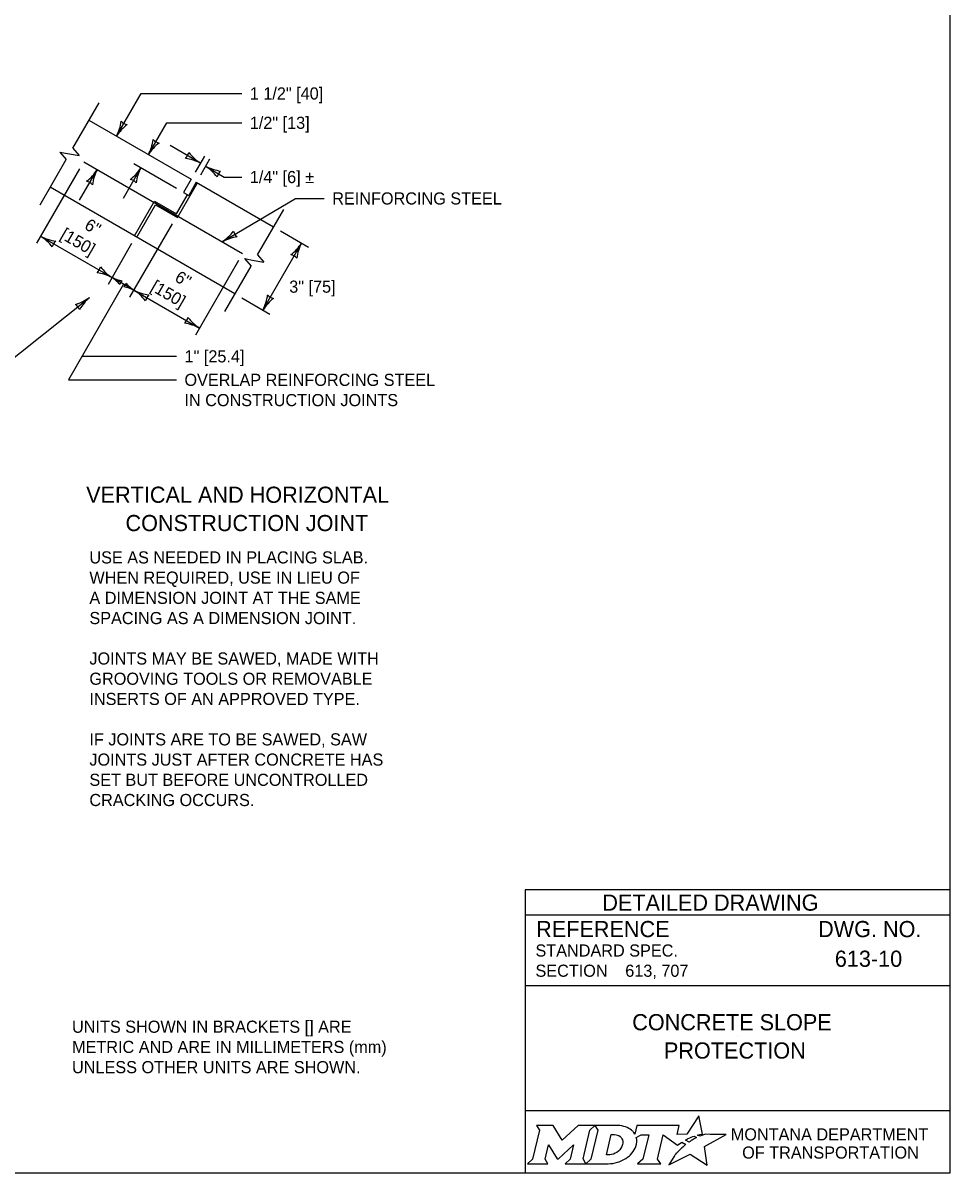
# Model space of a CAD drawing. Extents: x 49991.4 to 50021, y 49987.6 to 50011.4.
# Drawn here: x 50012.17 to 50016.75, y 49987.8 to 49993.49 of the extents above; entities that cross this region are included whole.
import ezdxf

# ---------------------------------------------------------------- set-up
doc = ezdxf.new("R2010")
doc.units = 0
for name, color, linetype in [('Default', 7, 'Continuous'), ('Level 1', 7, 'Continuous'), ('Level 2', 7, 'Continuous'), ('Level 3', 7, 'Continuous'), ('Level 5', 7, 'Continuous'), ('Level 6', 7, 'Continuous')]:
    doc.layers.add(name, color=color, linetype=linetype)

msp = doc.modelspace()

# ---------------------------------------------------------------- linework, layer by layer
at = {"layer": 'Default'}
for points in [[(50015.5126, 49987.9811), (50015.5023, 49987.9867), (50015.5139, 49987.9895), (50015.5255, 49987.9915), (50015.5081, 49988.0816), (50015.4486, 49987.9903), (50015.4013, 49987.9896), (50015.4116, 49988.0337), (50015.2024, 49988.0338), (50015.1923, 49987.9913), (50015.1865, 49987.9996)], [(50014.7056, 49988.0338), (50014.7197, 49988.0104), (50014.6862, 49987.8671), (50014.6605, 49987.8446), (50014.7621, 49987.8446), (50014.7486, 49987.8674), (50014.7648, 49987.9375), (50014.8085, 49987.8685), (50014.8138, 49987.8685), (50014.8889, 49987.938), (50014.8725, 49987.8669), (50014.8478, 49987.8449), (50014.9494, 49987.8449), (50014.9356, 49987.8682), (50014.9688, 49988.0106)], [(50014.9688, 49988.0106), (50014.9941, 49988.0338), (50014.9117, 49988.0338), (50014.8321, 49987.9608), (50014.7876, 49988.0335), (50014.7056, 49988.0338)], [(50015.1077, 49988.0338), (50014.9941, 49988.0338), (50015.0088, 49988.0109), (50014.9749, 49987.8671), (50014.9494, 49987.8449), (50015.06, 49987.8449)], [(50015.1317, 49987.9471), (50015.1305, 49987.939), (50015.1273, 49987.9297), (50015.1231, 49987.9215), (50015.1175, 49987.914), (50015.111, 49987.9071), (50015.1031, 49987.9008), (50015.0948, 49987.8961), (50015.0857, 49987.8922), (50015.0766, 49987.8899), (50015.0674, 49987.889), (50015.0515, 49987.889), (50015.0751, 49987.989), (50015.0911, 49987.989), (50015.0987, 49987.9884), (50015.1063, 49987.9865), (50015.1129, 49987.9835), (50015.119, 49987.9793), (50015.1238, 49987.9743), (50015.1275, 49987.9683), (50015.1302, 49987.9621), (50015.1318, 49987.9547), (50015.1318, 49987.9517), (50015.1317, 49987.9471)], [(50015.1991, 49987.9747), (50015.2237, 49987.9878), (50015.2606, 49987.9878), (50015.232, 49987.8673), (50015.2045, 49987.8446), (50015.3207, 49987.8446), (50015.3037, 49987.8675), (50015.3319, 49987.9877), (50015.4032, 49987.936), (50015.4243, 49987.9511), (50015.444, 49987.9402)], [(50015.3882, 49987.8843), (50015.3729, 49987.8599), (50015.3682, 49987.8524), (50015.3624, 49987.8438), (50015.3601, 49987.8395), (50015.4654, 49987.8926), (50015.5493, 49987.8375), (50015.5362, 49987.9302), (50015.6431, 49987.9886), (50015.5938, 49987.9894), (50015.5637, 49987.9898), (50015.5429, 49987.9901), (50015.5361, 49987.9886), (50015.5312, 49987.9874), (50015.5228, 49987.9851), (50015.5126, 49987.9811)], [(50015.4622, 49987.9535), (50015.4598, 49987.9518), (50015.4415, 49987.9614), (50015.4518, 49987.9671), (50015.4559, 49987.9693), (50015.4645, 49987.9733), (50015.4702, 49987.9759), (50015.4781, 49987.9789), (50015.4854, 49987.9816), (50015.4972, 49987.9742), (50015.4932, 49987.9721), (50015.4886, 49987.9696), (50015.4844, 49987.9674), (50015.4794, 49987.9645), (50015.4775, 49987.9634), (50015.4748, 49987.9618), (50015.4723, 49987.9604), (50015.47, 49987.9588), (50015.4674, 49987.957), (50015.4647, 49987.9552), (50015.4622, 49987.9535)], [(50015.1057, 49987.8522), (50015.1141, 49987.8548), (50015.1271, 49987.8602), (50015.1475, 49987.8712)], [(50015.4021, 49987.9004), (50015.4021, 49987.9004)]]:
    msp.add_lwpolyline(points, dxfattribs=at)
for centre, radius, start, end in [((50015.0868, 49987.9727), 0.1183, 300.9103, 339.1383), ((50015.1308, 49987.9554), 0.0709, 339.5329, 15.8582)]:
    msp.add_arc(centre, radius, start, end, dxfattribs=at)
for centre, major_axis, ratio, start_param, end_param in [((50015.1056, 49987.9864), (0.0834, -0.0037), 0.568097, 0.61298, 1.570796), ((50015.1612, 49987.9937), (0.0361, -0.0295), 0.469099, 1.225588, 1.570796), ((50015.4329, 49987.9305), (-0.0112, -0.0097), 0.021651, 3.157348, 6.283185), ((50015.3952, 49987.8923), (-0.00694, -0.00806), 0.008222, 0, 3.137361), ((50015.4119, 49987.9106), (-0.0098, -0.0102), 0.016458, 3.141593, 6.279097), ((50015.0603, 49987.9932), (0, 0.1484), 0.987302, 3.139398, 3.456847)]:
    msp.add_ellipse(centre, major_axis=major_axis, ratio=ratio, start_param=start_param, end_param=end_param, dxfattribs=at)
at = {"layer": 'Level 1'}
for p, q in [((50012.4923, 49993.006), (50012.9975, 49992.7141)), ((50012.4665, 49992.7998), (50013.2518, 49992.3466)), ((50012.9975, 49992.7141), (50012.9601, 49992.6492)), ((50013.2145, 49992.1471), (50012.3006, 49992.6744)), ((50012.9305, 49992.5249), (50013.029, 49992.696)), ((50012.9601, 49992.6492), (50012.986, 49992.6341)), ((50013.0234, 49992.6992), (50012.986, 49992.6341)), ((50013.0234, 49992.6992), (50013.4056, 49992.4784)), ((50012.7175, 49992.4339), (50012.8161, 49992.6058)), ((50012.8161, 49992.6058), (50012.9256, 49992.5426)), ((50012.9256, 49992.5426), (50012.9803, 49992.6374)), ((50012.7292, 49992.4271), (50012.8216, 49992.5876)), ((50012.8216, 49992.5876), (50012.9305, 49992.5249))]:
    msp.add_line(p, q, dxfattribs=at)
msp.add_lwpolyline([(49999.3835, 49998.9992), (50016.7501, 49998.9992), (50016.7501, 49987.7988), (49999.3835, 49987.7988)], close=True, dxfattribs=at)
at = {"layer": 'Level 3'}
for p, q in [((50012.6287, 49992.9272), (50012.751, 49993.1387)), ((50012.751, 49993.1387), (50013.2478, 49993.1387)), ((50012.7865, 49992.836), (50012.8771, 49992.9936)), ((50012.8771, 49992.9936), (50013.2478, 49992.9936)), ((50013.0437, 49992.7942), (50012.8934, 49992.8807)), ((50013.0637, 49992.8288), (50013.0175, 49992.7487)), ((50012.4465, 49992.7652), (50012.2337, 49992.3975)), ((50012.4465, 49992.6115), (50012.5332, 49992.7617)), ((50012.6626, 49992.6208), (50012.7492, 49992.7711)), ((50012.9255, 49992.6692), (50012.7146, 49992.7912)), ((50013.0892, 49992.8132), (50013.0434, 49992.7338)), ((50013.0692, 49992.7786), (50013.1618, 49992.7252)), ((50013.1618, 49992.7252), (50013.2478, 49992.7252)), ((50013.1509, 49992.4048), (50013.5142, 49992.6194)), ((50013.5142, 49992.6194), (50013.6555, 49992.6194)), ((50012.6946, 49992.1312), (50012.9048, 49992.4935)), ((50012.2537, 49992.4321), (50012.6066, 49992.2281)), ((50013.4402, 49992.4585), (50013.5782, 49992.3787)), ((50012.7033, 49992.3959), (50012.5868, 49992.1934)), ((50013.3526, 49992.0675), (50013.5436, 49992.3987)), ((50013.2318, 49992.312), (50013.0189, 49991.9438)), ((50012.6628, 49992.1958), (50012.3918, 49991.722)), ((50012.7147, 49992.1658), (50012.6066, 49992.2281)), ((50012.7147, 49992.1658), (50013.0389, 49991.9784)), ((50011.5449, 49991.371), (50012.4953, 49992.1298)), ((50013.2492, 49992.1271), (50013.3873, 49992.0475)), ((50012.4583, 49991.8384), (50012.9252, 49991.8384)), ((50012.3918, 49991.722), (50012.9247, 49991.722))]:
    msp.add_line(p, q, dxfattribs=at)
for centre, radius, start, end in [((50012.4215, 49993.0336), 0.233, 332.8074, 352.0572), ((50012.6929, 49993.0382), 0.0548, 222.1189, 257.8412), ((50012.8165, 49992.8081), 0.2223, 127.4361, 147.6196), ((50012.579, 49992.9421), 0.233, 332.9081, 352.158), ((50012.9744, 49992.7173), 0.2223, 127.5368, 147.7203), ((50012.8504, 49992.9472), 0.0548, 222.2196, 257.942), ((50012.9326, 49992.8581), 0.0548, 312.2277, 347.95), ((50012.9376, 49992.5867), 0.233, 62.9162, 82.166), ((50013.1624, 49992.9822), 0.2223, 217.5449, 237.7284), ((50012.3454, 49992.8807), 0.2223, 307.463, 327.6465), ((50012.3454, 49992.8807), 0.2223, 307.463, 327.6465), ((50012.7405, 49992.6553), 0.233, 152.8343, 172.0842), ((50012.7405, 49992.6553), 0.233, 152.8343, 172.0842), ((50012.5612, 49992.8898), 0.2223, 307.5459, 327.7294), ((50012.9566, 49992.6651), 0.233, 152.9172, 172.167), ((50012.9503, 49992.5907), 0.2223, 37.4907, 57.6742), ((50013.1755, 49992.9859), 0.233, 242.862, 262.1118), ((50012.4691, 49992.6507), 0.0548, 42.1458, 77.8682), ((50012.4691, 49992.6507), 0.0548, 42.1458, 77.8682), ((50012.6852, 49992.66), 0.0548, 42.2287, 77.9511), ((50013.1803, 49992.7145), 0.0548, 132.1735, 167.8958), ((50012.1346, 49992.2444), 0.2223, 37.4296, 57.6131), ((50012.3602, 49992.6393), 0.233, 242.8009, 262.0507), ((50013.0227, 49992.5993), 0.233, 303.3975, 322.6474), ((50013.256, 49992.2089), 0.2223, 98.0262, 118.2097), ((50013.2613, 49992.47), 0.0548, 192.709, 228.4314), ((50012.3647, 49992.368), 0.0548, 132.1124, 167.8347), ((50013.3557, 49992.5176), 0.2223, 307.4958, 327.6793), ((50013.7509, 49992.2925), 0.233, 152.8671, 172.117), ((50013.4795, 49992.2877), 0.0548, 42.1786, 77.901), ((50012.4958, 49992.2922), 0.0548, 312.1124, 347.8347), ((50012.5003, 49992.0208), 0.233, 62.8009, 82.0507), ((50012.7259, 49992.4158), 0.2223, 217.4296, 237.6131), ((50012.5275, 49992.1028), 0.1482, 37.4804, 57.6639), ((50012.6777, 49992.3663), 0.1553, 242.8517, 262.1016), ((50012.6808, 49992.1853), 0.0365, 132.1632, 167.8856), ((50012.6406, 49992.2085), 0.0365, 312.1632, 347.8856), ((50012.794, 49992.291), 0.1482, 217.4804, 237.6639), ((50012.6438, 49992.0276), 0.1553, 62.8517, 82.1016), ((50012.5956, 49991.9781), 0.2223, 37.4244, 57.6079), ((50012.8212, 49992.373), 0.233, 242.7957, 262.0456), ((50012.8257, 49992.1016), 0.0548, 132.1072, 167.8296), ((50013.1453, 49992.1737), 0.233, 332.8671, 352.117), ((50013.4167, 49992.1786), 0.0548, 222.1786, 257.901), ((50012.3638, 49992.3091), 0.2223, 286.0616, 306.2451), ((50012.3951, 49992.0498), 0.0548, 20.7444, 56.4667), ((50012.6495, 49991.9551), 0.233, 131.4329, 150.6827), ((50013.5405, 49991.9486), 0.2223, 127.4958, 147.6793), ((50012.9279, 49992.0426), 0.0548, 312.1072, 347.8296), ((50013.158, 49992.1662), 0.2223, 217.4244, 237.6079), ((50012.9324, 49991.7712), 0.233, 62.7957, 82.0456)]:
    msp.add_arc(centre, radius, start, end, dxfattribs=at)
at = {"layer": 'Level 5'}
for p, q in [((50016.7501, 49989.1988), (50014.6501, 49989.1988)), ((50014.6501, 49989.1988), (50014.6501, 49987.7988)), ((50016.7501, 49989.0738), (50014.6501, 49989.0738)), ((50016.3862, 49988.8587), (50016.3862, 49988.8587)), ((50015.1444, 49988.7993), (50015.1444, 49988.7993)), ((50016.7501, 49988.7238), (50014.6501, 49988.7238)), ((50015.7001, 49988.4747), (50015.7001, 49988.4747)), ((50016.7501, 49988.1057), (50014.6501, 49988.1057))]:
    msp.add_line(p, q, dxfattribs=at)
at = {"layer": 'Level 6'}
for p, q in [((50012.4126, 49992.8682), (50012.5423, 49993.0926)), ((50012.3487, 49992.849), (50012.3964, 49992.8402)), ((50012.3487, 49992.849), (50012.3802, 49992.8121)), ((50012.3964, 49992.8402), (50012.4441, 49992.8314)), ((50012.4126, 49992.8683), (50012.4441, 49992.8314)), ((50012.2506, 49992.5878), (50012.3802, 49992.8121)), ((50013.3262, 49992.3409), (50013.4555, 49992.565)), ((50013.2623, 49992.3216), (50013.31, 49992.3128)), ((50013.2623, 49992.3216), (50013.2938, 49992.2847)), ((50013.31, 49992.3128), (50013.3577, 49992.304)), ((50013.3262, 49992.3409), (50013.3577, 49992.304)), ((50013.1646, 49992.0605), (50013.2938, 49992.2847))]:
    msp.add_line(p, q, dxfattribs=at)

# ---------------------------------------------------------------- texts
at = {"layer": 'Default'}
for s, p in [('MONTANA DEPARTMENT', (50015.6663, 49987.96)), ('OF TRANSPORTATION', (50015.7225, 49987.87))]:
    msp.add_text(s, height=0.06, dxfattribs=at).set_placement(p)
at = {"layer": 'Level 2'}
for s, height, p in [('1 1/2" [40]', 0.06, (50013.2878, 49993.1087)), ('1/2" [13]', 0.06, (50013.2878, 49992.9636)), ('1/4" [6] ±', 0.06, (50013.2878, 49992.6952)), ('REINFORCING STEEL', 0.06, (50013.6955, 49992.5894)), ('3" [75]', 0.06, (50013.4828, 49992.1531)), ('1" [25.4]', 0.06, (50012.9652, 49991.8084)), ('OVERLAP REINFORCING STEEL', 0.06, (50012.9647, 49991.692)), ('IN CONSTRUCTION JOINTS', 0.06, (50012.9647, 49991.592)), ('VERTICAL AND HORIZONTAL', 0.08, (50012.4788, 49991.1138)), ('CONSTRUCTION JOINT', 0.08, (50012.6732, 49990.9738)), ('USE AS NEEDED IN PLACING SLAB.', 0.06, (50012.4947, 49990.8138)), ('WHEN REQUIRED, USE IN LIEU OF', 0.06, (50012.4947, 49990.7138)), ('A DIMENSION JOINT AT THE SAME', 0.06, (50012.4947, 49990.6138)), ('SPACING AS A DIMENSION JOINT.', 0.06, (50012.4947, 49990.5138)), ('JOINTS MAY BE SAWED, MADE WITH', 0.06, (50012.4947, 49990.3138)), ('GROOVING TOOLS OR REMOVABLE', 0.06, (50012.4947, 49990.2138)), ('INSERTS OF AN APPROVED TYPE.', 0.06, (50012.4947, 49990.1138)), ('IF JOINTS ARE TO BE SAWED, SAW', 0.06, (50012.4947, 49989.9138)), ('JOINTS JUST AFTER CONCRETE HAS', 0.06, (50012.4947, 49989.8138)), ('SET BUT BEFORE UNCONTROLLED', 0.06, (50012.4947, 49989.7138)), ('CRACKING OCCURS.', 0.06, (50012.4947, 49989.6138)), ('613-10', 0.08, (50016.1806, 49988.8187)), ('613, 707', 0.06, (50015.1444, 49988.7693)), ('UNITS SHOWN IN BRACKETS [] ARE ', 0.06, (50012.4089, 49988.4924)), ('CONCRETE SLOPE', 0.08, (50015.1787, 49988.5047)), ('METRIC AND ARE IN MILLIMETERS (mm) ', 0.06, (50012.4089, 49988.3924)), ('PROTECTION', 0.08, (50015.3356, 49988.3647)), ('UNLESS OTHER UNITS ARE SHOWN.', 0.06, (50012.4089, 49988.2924))]:
    msp.add_text(s, height=height, dxfattribs=at).set_placement(p)
for s, rotation, p in [('[150]', 329.9258, (50012.3463, 49992.4249)), ('6"', 329.9258, (50012.4655, 49992.4714)), ('6"', 329.9179, (50012.9122, 49992.2134)), ('[150]', 329.9179, (50012.7929, 49992.1669))]:
    msp.add_text(s, height=0.06, rotation=rotation, dxfattribs=at).set_placement(p)
at = {"layer": 'Level 5'}
for s, height, p in [('DETAILED DRAWING', 0.0799, (50015.0311, 49989.0963)), ('REFERENCE', 0.08, (50014.7037, 49988.9654)), ('DWG. NO.', 0.08, (50016.0979, 49988.9654)), ('STANDARD SPEC.', 0.06, (50014.7004, 49988.8694)), ('SECTION', 0.06, (50014.7004, 49988.7694))]:
    msp.add_text(s, height=height, dxfattribs=at).set_placement(p)

doc.saveas('drawing.dxf')
